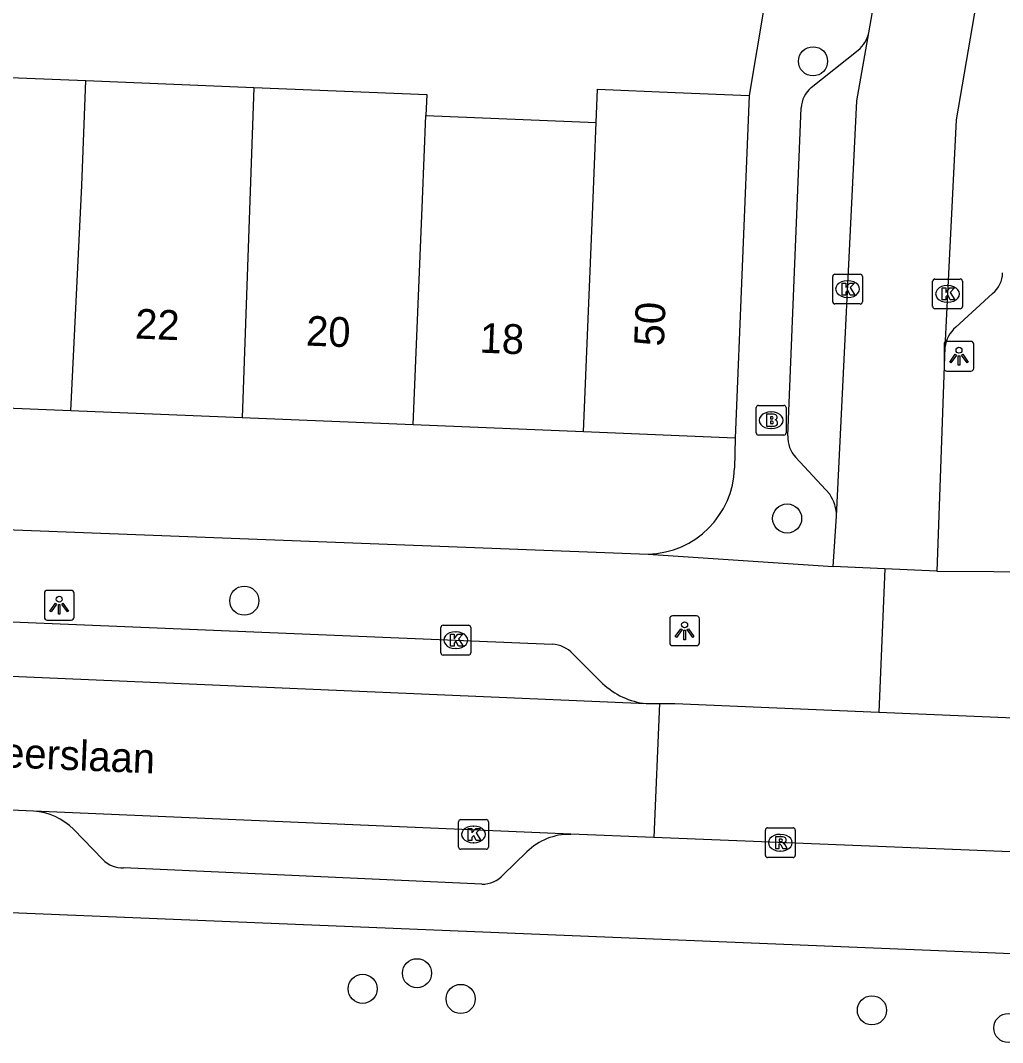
# Model space of a CAD drawing. Extents: x 159822 to 160765, y 380693 to 381634.
# Drawn here: x 160082.34 to 160115.31, y 380860.77 to 380895.1 of the extents above; entities that cross this region are included whole.
import ezdxf

# ---------------------------------------------------------------- set-up
doc = ezdxf.new("R2010")
doc.units = 0
for name, color, linetype in [('IMGEO_Boom', 7, 'Continuous'), ('IMGEO_Brandkraan', 7, 'Continuous'), ('IMGEO_Kolk', 7, 'Continuous'), ('IMGEO_Lichtpunt', 7, 'Continuous'), ('IMGEO_Openbare_ruimte_label', 7, 'Continuous'), ('IMGEO_Pand', 7, 'Continuous'), ('IMGEO_Pand_nummerreeks', 7, 'Continuous'), ('IMGEO_Rijbaan_lokaal_open', 7, 'Continuous'), ('IMGEO_Rioolput', 7, 'Continuous'), ('IMGEO_Voetpad_open', 7, 'Continuous')]:
    doc.layers.add(name, color=color, linetype=linetype)

msp = doc.modelspace()

# ---------------------------------------------------------------- linework, layer by layer
at = {"layer": 'IMGEO_Boom'}
for centre in [(160108.949, 380893.73), (160108.078, 380878.374), (160089.856, 380875.615), (160095.654, 380863.103), (160093.829, 380862.579), (160097.12, 380862.24), (160110.926, 380861.858), (160115.507, 380861.264)]:
    msp.add_circle(centre, 0.489, dxfattribs=at)
at = {"layer": 'IMGEO_Brandkraan'}
for p, q in [((160107.043, 380881.248), (160107.043, 380882.1)), ((160107.118, 380882.174), (160107.97, 380882.174)), ((160107.531, 380881.954), (160107.556, 380881.954)), ((160108.044, 380882.1), (160108.044, 380881.248)), ((160107.554, 380881.394), (160107.529, 380881.394)), ((160107.97, 380881.174), (160107.118, 380881.174))]:
    msp.add_line(p, q, dxfattribs=at)
for points in [[(160107.043, 380881.248), (160107.043, 380882.1)], [(160107.118, 380882.174), (160107.97, 380882.174)], [(160108.044, 380882.1), (160108.044, 380881.248)], [(160107.391, 380881.874), (160107.391, 380881.474), (160107.604, 380881.474)], [(160107.622, 380881.874), (160107.391, 380881.874)], [(160107.57, 380881.793), (160107.516, 380881.793), (160107.516, 380881.717)], [(160107.516, 380881.717), (160107.569, 380881.717)], [(160107.578, 380881.641), (160107.516, 380881.641), (160107.516, 380881.56)], [(160107.516, 380881.56), (160107.578, 380881.56)], [(160107.97, 380881.174), (160107.118, 380881.174)]]:
    msp.add_lwpolyline(points, dxfattribs=at)
for centre, radius, start, end in [((160107.12, 380882.098), 0.0765, 91.552, 178.448), ((160107.12, 380882.098), 0.0765, 91.552, 178.448), ((160107.968, 380882.098), 0.0765, 1.552, 88.448), ((160107.968, 380882.098), 0.0765, 1.552, 88.448), ((160107.571, 380881.755), 0.0379, 267.8285, 90.9355), ((160107.579, 380881.6), 0.0404, 269.8759, 90.5077), ((160107.626, 380881.729), 0.145, 59.4692, 91.5367), ((160107.651, 380881.776), 0.0922, 285.5137, 58.1501), ((160107.656, 380881.584), 0.105, 301.3115, 78.989), ((160107.12, 380881.25), 0.0765, 181.552, 268.448), ((160107.12, 380881.25), 0.0765, 181.552, 268.448), ((160107.61, 380881.725), 0.251, 268.6676, 293.5347), ((160107.968, 380881.25), 0.0765, 271.552, 358.448), ((160107.968, 380881.25), 0.0765, 271.552, 358.448)]:
    msp.add_arc(centre, radius, start, end, dxfattribs=at)
for centre, major_axis, ratio, start_param, end_param in [((160107.53, 380881.674), (-0.387, 0.002), 0.722429, 4.712389, 7.853982), ((160107.555, 380881.674), (-0.39, 0.002), 0.717154, 1.570796, 4.712389)]:
    msp.add_ellipse(centre, major_axis=major_axis, ratio=ratio, start_param=start_param, end_param=end_param, dxfattribs=at)
at = {"layer": 'IMGEO_Kolk'}
for p, q in [((160109.608, 380885.653), (160109.608, 380886.505)), ((160109.683, 380886.579), (160110.535, 380886.579)), ((160110.609, 380886.505), (160110.609, 380885.653)), ((160113.04, 380886.418), (160113.892, 380886.418)), ((160110.096, 380886.359), (160110.121, 380886.359)), ((160112.965, 380885.492), (160112.965, 380886.344)), ((160113.453, 380886.198), (160113.478, 380886.198)), ((160113.966, 380886.344), (160113.966, 380885.492)), ((160110.119, 380885.799), (160110.094, 380885.799)), ((160110.535, 380885.579), (160109.683, 380885.579)), ((160113.892, 380885.418), (160113.04, 380885.418)), ((160113.476, 380885.638), (160113.451, 380885.638)), ((160096.53, 380874.788), (160097.382, 380874.788)), ((160096.455, 380873.862), (160096.455, 380874.714)), ((160096.943, 380874.568), (160096.968, 380874.568)), ((160097.456, 380874.714), (160097.456, 380873.862)), ((160097.382, 380873.788), (160096.53, 380873.788)), ((160096.966, 380874.008), (160096.941, 380874.008)), ((160097.127, 380868.266), (160097.979, 380868.266)), ((160097.052, 380867.34), (160097.052, 380868.192)), ((160097.54, 380868.046), (160097.565, 380868.046)), ((160098.053, 380868.192), (160098.053, 380867.34)), ((160097.979, 380867.266), (160097.127, 380867.266)), ((160097.563, 380867.486), (160097.538, 380867.486))]:
    msp.add_line(p, q, dxfattribs=at)
for points in [[(160109.608, 380885.653), (160109.608, 380886.505)], [(160109.683, 380886.579), (160110.535, 380886.579)], [(160110.609, 380886.505), (160110.609, 380885.653)], [(160113.04, 380886.418), (160113.892, 380886.418)], [(160109.929, 380886.279), (160110.052, 380886.279), (160110.052, 380886.128), (160110.182, 380886.279), (160110.346, 380886.279), (160110.2, 380886.128), (160110.353, 380885.879), (160110.201, 380885.879), (160110.116, 380886.043), (160110.052, 380885.976), (160110.052, 380885.879), (160109.929, 380885.879), (160109.929, 380886.279)], [(160112.965, 380885.492), (160112.965, 380886.344)], [(160113.286, 380886.118), (160113.409, 380886.118), (160113.409, 380885.967), (160113.539, 380886.118), (160113.703, 380886.118), (160113.557, 380885.967), (160113.71, 380885.718), (160113.558, 380885.718), (160113.473, 380885.882), (160113.409, 380885.815), (160113.409, 380885.718), (160113.286, 380885.718), (160113.286, 380886.118)], [(160113.966, 380886.344), (160113.966, 380885.492)], [(160110.535, 380885.579), (160109.683, 380885.579)], [(160113.892, 380885.418), (160113.04, 380885.418)], [(160096.53, 380874.788), (160097.382, 380874.788)], [(160096.455, 380873.862), (160096.455, 380874.714)], [(160096.776, 380874.488), (160096.899, 380874.488), (160096.899, 380874.337), (160097.029, 380874.488), (160097.193, 380874.488), (160097.047, 380874.337), (160097.2, 380874.088), (160097.048, 380874.088), (160096.963, 380874.252), (160096.899, 380874.185), (160096.899, 380874.088), (160096.776, 380874.088), (160096.776, 380874.488)], [(160097.456, 380874.714), (160097.456, 380873.862)], [(160097.382, 380873.788), (160096.53, 380873.788)], [(160097.127, 380868.266), (160097.979, 380868.266)], [(160097.052, 380867.34), (160097.052, 380868.192)], [(160097.373, 380867.966), (160097.496, 380867.966), (160097.496, 380867.815), (160097.626, 380867.966), (160097.79, 380867.966), (160097.644, 380867.815), (160097.797, 380867.566), (160097.645, 380867.566), (160097.56, 380867.73), (160097.496, 380867.663), (160097.496, 380867.566), (160097.373, 380867.566), (160097.373, 380867.966)], [(160098.053, 380868.192), (160098.053, 380867.34)], [(160097.979, 380867.266), (160097.127, 380867.266)]]:
    msp.add_lwpolyline(points, dxfattribs=at)
for centre, start, end in [((160109.685, 380886.503), 91.552, 178.448), ((160109.685, 380886.503), 91.552, 178.448), ((160110.533, 380886.503), 1.552, 88.448), ((160110.533, 380886.503), 1.552, 88.448), ((160113.042, 380886.342), 91.552, 178.448), ((160113.042, 380886.342), 91.552, 178.448), ((160113.89, 380886.342), 1.552, 88.448), ((160113.89, 380886.342), 1.552, 88.448), ((160109.685, 380885.655), 181.552, 268.448), ((160109.685, 380885.655), 181.552, 268.448), ((160110.533, 380885.655), 271.552, 358.448), ((160110.533, 380885.655), 271.552, 358.448), ((160113.042, 380885.494), 181.552, 268.448), ((160113.042, 380885.494), 181.552, 268.448), ((160113.89, 380885.494), 271.552, 358.448), ((160113.89, 380885.494), 271.552, 358.448), ((160096.532, 380874.712), 91.552, 178.448), ((160096.532, 380874.712), 91.552, 178.448), ((160097.38, 380874.712), 1.552, 88.448), ((160097.38, 380874.712), 1.552, 88.448), ((160096.532, 380873.864), 181.552, 268.448), ((160096.532, 380873.864), 181.552, 268.448), ((160097.38, 380873.864), 271.552, 358.448), ((160097.38, 380873.864), 271.552, 358.448), ((160097.129, 380868.19), 91.552, 178.448), ((160097.129, 380868.19), 91.552, 178.448), ((160097.977, 380868.19), 1.552, 88.448), ((160097.977, 380868.19), 1.552, 88.448), ((160097.129, 380867.342), 181.552, 268.448), ((160097.129, 380867.342), 181.552, 268.448), ((160097.977, 380867.342), 271.552, 358.448), ((160097.977, 380867.342), 271.552, 358.448)]:
    msp.add_arc(centre, 0.0765, start, end, dxfattribs=at)
for centre, major_axis, ratio, start_param, end_param in [((160110.095, 380886.079), (-0.387, 0.002), 0.722429, 4.712389, 7.853982), ((160110.12, 380886.079), (-0.39, 0.002), 0.717154, 1.570796, 4.712389), ((160113.452, 380885.918), (-0.387, 0.002), 0.722429, 4.712389, 7.853982), ((160113.477, 380885.918), (-0.39, 0.002), 0.717154, 1.570796, 4.712389), ((160096.942, 380874.288), (-0.387, 0.002), 0.722429, 4.712389, 7.853982), ((160096.967, 380874.288), (-0.39, 0.002), 0.717154, 1.570796, 4.712389), ((160097.539, 380867.766), (-0.387, 0.002), 0.722429, 4.712389, 7.853982), ((160097.564, 380867.766), (-0.39, 0.002), 0.717154, 1.570796, 4.712389)]:
    msp.add_ellipse(centre, major_axis=major_axis, ratio=ratio, start_param=start_param, end_param=end_param, dxfattribs=at)
at = {"layer": 'IMGEO_Lichtpunt'}
for p, q in [((160113.349, 380884.227), (160113.349, 380883.42)), ((160113.349, 380884.227), (160113.349, 380883.42)), ((160114.251, 380884.322), (160113.443, 380884.322)), ((160114.251, 380884.322), (160113.443, 380884.322)), ((160114.345, 380883.42), (160114.345, 380884.227)), ((160114.345, 380883.42), (160114.345, 380884.227)), ((160113.443, 380883.326), (160114.251, 380883.326)), ((160113.443, 380883.326), (160114.251, 380883.326)), ((160083.144, 380875.866), (160083.144, 380875.059)), ((160083.144, 380875.866), (160083.144, 380875.059)), ((160084.046, 380875.961), (160083.238, 380875.961)), ((160084.046, 380875.961), (160083.238, 380875.961)), ((160084.14, 380875.059), (160084.14, 380875.866)), ((160084.14, 380875.059), (160084.14, 380875.866)), ((160105.041, 380875.103), (160104.233, 380875.103)), ((160105.041, 380875.103), (160104.233, 380875.103)), ((160083.238, 380874.965), (160084.046, 380874.965)), ((160083.238, 380874.965), (160084.046, 380874.965)), ((160104.139, 380875.008), (160104.139, 380874.201)), ((160104.139, 380875.008), (160104.139, 380874.201)), ((160105.135, 380874.201), (160105.135, 380875.008)), ((160105.135, 380874.201), (160105.135, 380875.008)), ((160104.233, 380874.107), (160105.041, 380874.107)), ((160104.233, 380874.107), (160105.041, 380874.107))]:
    msp.add_line(p, q, dxfattribs=at)
for points in [[(160113.723, 380883.891), (160113.762, 380883.863), (160113.574, 380883.601), (160113.536, 380883.628), (160113.723, 380883.891)], [(160113.825, 380883.843), (160113.872, 380883.843), (160113.872, 380883.521), (160113.825, 380883.521), (160113.825, 380883.843)], [(160113.935, 380883.863), (160113.973, 380883.89), (160114.16, 380883.628), (160114.121, 380883.6), (160113.935, 380883.863)], [(160083.518, 380875.53), (160083.557, 380875.502), (160083.369, 380875.24), (160083.331, 380875.267), (160083.518, 380875.53)], [(160083.62, 380875.482), (160083.667, 380875.482), (160083.667, 380875.16), (160083.62, 380875.16), (160083.62, 380875.482)], [(160083.73, 380875.502), (160083.768, 380875.529), (160083.955, 380875.267), (160083.916, 380875.239), (160083.73, 380875.502)], [(160104.513, 380874.672), (160104.552, 380874.644), (160104.364, 380874.382), (160104.326, 380874.409), (160104.513, 380874.672)], [(160104.615, 380874.624), (160104.662, 380874.624), (160104.662, 380874.302), (160104.615, 380874.302), (160104.615, 380874.624)], [(160104.725, 380874.644), (160104.763, 380874.671), (160104.95, 380874.409), (160104.911, 380874.381), (160104.725, 380874.644)]]:
    msp.add_lwpolyline(points, dxfattribs=at)
for centre in [(160113.848, 380884.025), (160083.643, 380875.664), (160104.638, 380874.806)]:
    msp.add_circle(centre, 0.0994, dxfattribs=at)
for centre, start, end in [((160113.443, 380884.227), 90, 180), ((160113.443, 380884.227), 90, 180), ((160114.251, 380884.227), 0, 90), ((160114.251, 380884.227), 0, 90), ((160113.443, 380883.42), 180, 270), ((160113.443, 380883.42), 180, 270), ((160114.251, 380883.42), 270, 0), ((160114.251, 380883.42), 270, 360), ((160083.238, 380875.866), 90, 180), ((160083.238, 380875.866), 90, 180), ((160084.046, 380875.866), 0, 90), ((160084.046, 380875.866), 0, 90), ((160104.233, 380875.008), 90, 180), ((160104.233, 380875.008), 90, 180), ((160105.041, 380875.008), 0, 90), ((160105.041, 380875.008), 0, 90), ((160083.238, 380875.059), 180, 270), ((160083.238, 380875.059), 180, 270), ((160084.046, 380875.059), 270, 0), ((160084.046, 380875.059), 270, 360), ((160104.233, 380874.201), 180, 270), ((160104.233, 380874.201), 180, 270), ((160105.041, 380874.201), 270, 0), ((160105.041, 380874.201), 270, 360)]:
    msp.add_arc(centre, 0.0946, start, end, dxfattribs=at)
at = {"layer": 'IMGEO_Pand'}
for points in [[(160078.602, 380889.801), (160081.274, 380889.691), (160081.418, 380893.212), (160084.542, 380893.084)], [(160084.036, 380881.987), (160084.398, 380889.563), (160084.542, 380893.084)], [(160084.542, 380893.084), (160090.175, 380892.853)], [(160090.175, 380892.853), (160089.781, 380881.751)], [(160090.175, 380892.853), (160095.982, 380892.615), (160095.953, 380891.905)], [(160101.668, 380891.67), (160101.714, 380892.793), (160104.319, 380892.686), (160106.808, 380892.584)], [(160106.808, 380892.584), (160106.335, 380881.071)], [(160095.526, 380881.515), (160095.837, 380889.093), (160095.953, 380891.905)], [(160095.953, 380891.905), (160101.668, 380891.67)], [(160101.239, 380881.28), (160101.552, 380888.858), (160101.668, 380891.67)], [(160084.036, 380881.987), (160078.29, 380882.223)], [(160089.781, 380881.751), (160084.036, 380881.987)], [(160095.526, 380881.515), (160089.781, 380881.751)], [(160101.239, 380881.28), (160095.526, 380881.515)], [(160106.335, 380881.071), (160101.239, 380881.28)]]:
    msp.add_lwpolyline(points, dxfattribs=at)
at = {"layer": 'IMGEO_Rijbaan_lokaal_open'}
for points in [[(160123.634, 380949.453), (160113.751, 380891.769), (160113.376, 380884.116)], [(160110.823, 380894.689), (160111.391, 380897.971), (160112.145, 380902.423), (160112.512, 380904.594)], [(160109.736, 380878.45), (160110.421, 380892.404), (160110.823, 380894.689)], [(160113.376, 380884.116), (160113.106, 380876.611)], [(160109.622, 380876.765), (160109.736, 380878.45)], [(160111.364, 380876.688), (160109.622, 380876.765)], [(160113.106, 380876.611), (160111.364, 380876.688)], [(160054.971, 380874.246), (160103.343, 380872.158)], [(160103.343, 380872.158), (160103.797, 380872.159)], [(160103.797, 380872.159), (160103.608, 380867.658)], [(160103.797, 380872.159), (160104.313, 380872.161), (160111.159, 380871.87)], [(160111.159, 380871.87), (160117.285, 380871.609), (160117.994, 380871.561)], [(160082.781, 380868.547), (160075.23, 380868.883)], [(160100.815, 380867.768), (160082.781, 380868.547)], [(160103.608, 380867.658), (160100.815, 380867.768)], [(160117.81, 380867.096), (160103.608, 380867.658)]]:
    msp.add_lwpolyline(points, dxfattribs=at)
at = {"layer": 'IMGEO_Rioolput'}
for p, q in [((160107.35, 380867.061), (160107.35, 380867.913)), ((160107.425, 380867.987), (160108.277, 380867.987)), ((160108.351, 380867.913), (160108.351, 380867.061)), ((160107.838, 380867.767), (160107.863, 380867.767)), ((160107.861, 380867.207), (160107.836, 380867.207)), ((160108.277, 380866.987), (160107.425, 380866.987))]:
    msp.add_line(p, q, dxfattribs=at)
for points in [[(160107.35, 380867.061), (160107.35, 380867.913)], [(160107.425, 380867.987), (160108.277, 380867.987)], [(160108.351, 380867.913), (160108.351, 380867.061)], [(160107.939, 380867.685), (160107.687, 380867.687), (160107.687, 380867.287)], [(160107.865, 380867.606), (160107.811, 380867.606), (160107.811, 380867.525)], [(160107.811, 380867.525), (160107.863, 380867.525)], [(160107.687, 380867.287), (160107.811, 380867.287), (160107.811, 380867.449), (160107.822, 380867.449)], [(160107.869, 380867.42), (160107.94, 380867.287), (160108.08, 380867.287), (160108.015, 380867.413)], [(160108.277, 380866.987), (160107.425, 380866.987)]]:
    msp.add_lwpolyline(points, dxfattribs=at)
for centre, radius, start, end in [((160107.427, 380867.911), 0.0765, 91.552, 178.448), ((160107.427, 380867.911), 0.0765, 91.552, 178.448), ((160108.275, 380867.911), 0.0765, 1.552, 88.448), ((160108.275, 380867.911), 0.0765, 1.552, 88.448), ((160107.847, 380867.714), 0.19, 274.7715, 282.9687), ((160107.871, 380867.51), 0.0964, 77.0061, 93.1865), ((160107.885, 380867.567), 0.0378, 276.6634, 79.6772), ((160107.938, 380867.575), 0.109, 350.3612, 89.416), ((160107.936, 380867.575), 0.112, 277.5842, 350.9817), ((160107.821, 380867.396), 0.0533, 26.0293, 88.6989), ((160107.92, 380867.36), 0.108, 29.5134, 73.7905), ((160107.427, 380867.063), 0.0765, 181.552, 268.448), ((160107.427, 380867.063), 0.0765, 181.552, 268.448), ((160108.275, 380867.063), 0.0765, 271.552, 358.448), ((160108.275, 380867.063), 0.0765, 271.552, 358.448)]:
    msp.add_arc(centre, radius, start, end, dxfattribs=at)
for centre, major_axis, ratio, start_param, end_param in [((160107.837, 380867.487), (-0.387, 0.002), 0.722429, 4.712389, 7.853982), ((160107.862, 380867.487), (-0.39, 0.002), 0.717154, 1.570796, 4.712389)]:
    msp.add_ellipse(centre, major_axis=major_axis, ratio=ratio, start_param=start_param, end_param=end_param, dxfattribs=at)
at = {"layer": 'IMGEO_Voetpad_open'}
for points in [[(160108.066, 380900.123), (160106.808, 380892.584)], [(160108.889, 380892.852), (160110.459, 380894.099)], [(160108.099, 380881.155), (160108.554, 380892.164)], [(160114.974, 380885.929), (160113.743, 380884.8)], [(160106.335, 380881.071), (160106.316, 380880.068)], [(160109.508, 380879.19), (160108.373, 380880.423)], [(160058.577, 380878.925), (160062.579, 380878.745), (160103.417, 380877.179)], [(160103.417, 380877.179), (160109.622, 380876.765)], [(160111.364, 380876.688), (160111.159, 380871.87)], [(160113.106, 380876.611), (160118.85, 380876.572)], [(160057.142, 380875.938), (160100.196, 380874.153)], [(160100.888, 380873.827), (160101.886, 380872.837)], [(160169.444, 380861.549), (160005.773, 380868.257), (159996.586, 380868.629), (159996.603, 380869.516), (159993.946, 380869.644), (159993.895, 380868.739), (159985.923, 380869.026)], [(160085.107, 380866.927), (160084.127, 380867.939)], [(160099.346, 380867.182), (160098.551, 380866.407)], [(160097.829, 380866.095), (160085.806, 380866.638)]]:
    msp.add_lwpolyline(points, dxfattribs=at)
for centre, radius, start, end in [((160109.81, 380894.907), 1.036, 308.7889, 347.8661), ((160109.503, 380892.128), 0.949, 130.273, 177.8023), ((160114.41, 380886.632), 0.901, 308.7417, 359.5862), ((160114.42, 380883.996), 1.051, 130.1196, 173.4489), ((160109.118, 380881.119), 1.02, 177.9942, 223.0492), ((160103.33, 380880.165), 2.987, 271.6605, 358.1415), ((160108.405, 380878.445), 1.331, 0.2098, 34.0392), ((160100.151, 380873.159), 0.995, 42.1581, 87.3918), ((160103.612, 380874.637), 2.493, 226.2088, 263.8177), ((160082.649, 380866.46), 2.091, 45.0109, 86.3708), ((160100.779, 380865.724), 2.044, 88.9906, 134.5046), ((160085.766, 380867.53), 0.893, 222.4814, 272.5935), ((160097.836, 380867.07), 0.975, 269.576, 317.1656)]:
    msp.add_arc(centre, radius, start, end, dxfattribs=at)

# ---------------------------------------------------------------- texts
at = {"layer": 'IMGEO_Openbare_ruimte_label'}
msp.add_text('Bernard Zweerslaan', height=1, rotation=357.6498, dxfattribs=at).set_placement((160074.809, 380870.306))
at = {"layer": 'IMGEO_Pand_nummerreeks'}
for s, rotation, p in [('22', 357.6485, (160086.175, 380884.422)), ('50', 87.6454, (160103.939, 380884.141)), ('20', 357.6509, (160091.916, 380884.185)), ('18', 357.6509, (160097.743, 380883.947))]:
    msp.add_text(s, height=1, rotation=rotation, dxfattribs=at).set_placement(p)

doc.saveas('drawing.dxf')
